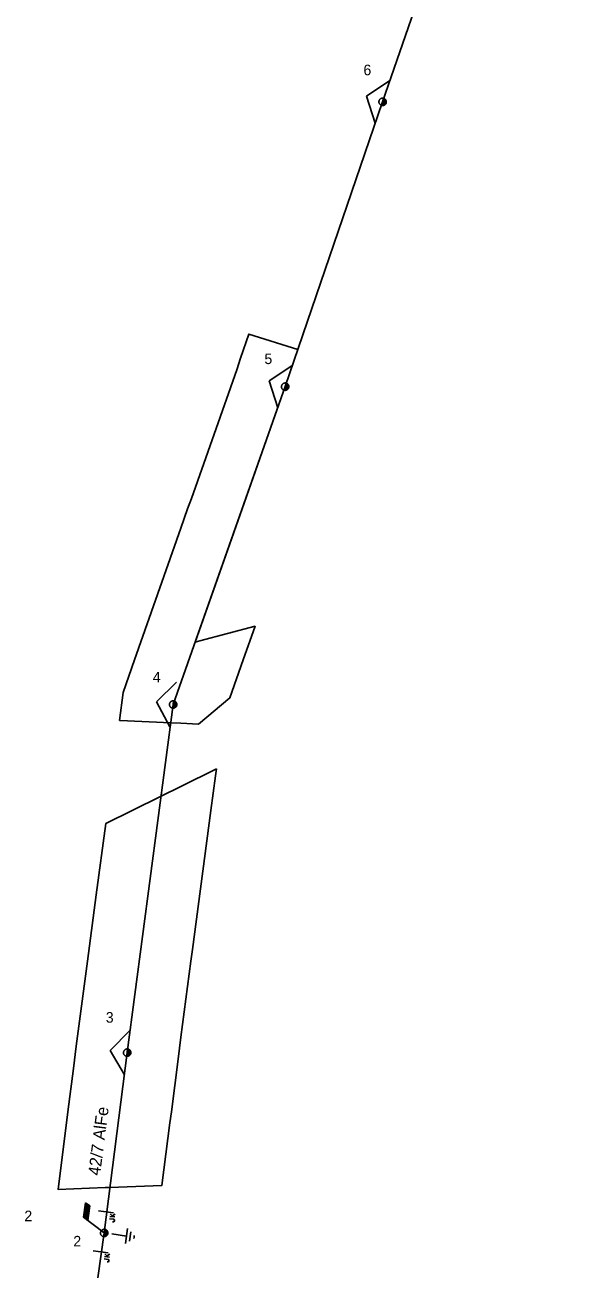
# Model space of a CAD drawing. Extents: x -536397 to -535454, y -1201642 to -1200953.
# Drawn here: x -535913.3 to -535821.2, y -1201640.1 to -1201432.2 of the extents above; entities that cross this region are included whole.
import ezdxf

# ---------------------------------------------------------------- set-up
doc = ezdxf.new("R2010")
doc.units = 0
for name, color, linetype in [('Default', 7, 'Continuous'), ('Vrstva 11', 7, 'Continuous'), ('Vrstva 12', 7, 'Continuous'), ('Vrstva 13', 7, 'Continuous'), ('Vrstva 14', 7, 'Continuous'), ('Vrstva 15', 7, 'Continuous'), ('Vrstva 18', 7, 'Continuous'), ('Vrstva 2', 7, 'Continuous'), ('Vrstva 35', 7, 'Continuous'), ('Vrstva 52', 7, 'Continuous'), ('Vrstva 53', 7, 'Continuous')]:
    doc.layers.add(name, color=color, linetype=linetype)

# ---------------------------------------------------------------- blocks, each defined once
blk = doc.blocks.new('VN840')
at = {"layer": 'Vrstva 15'}
for points in [[(-0.01, 1.41), (-0.01, -1.09)], [(-1.51, -1.24), (-1.51, -1.15)], [(-1.48, -1.35), (-1.51, -1.24)], [(-1.33, -1.42), (-1.48, -1.35)], [(-1.27, -1.42), (-1.33, -1.42)], [(-1.13, -1.35), (-1.27, -1.42)], [(-1.09, -1.24), (-1.13, -1.35)], [(-1.09, -0.59), (-1.09, -1.24)], [(-0.68, -0.59), (-0.68, -1.42)], [(-0.68, -1.11), (-0.27, -0.59)], [(-0.54, -0.94), (-0.2, -1.42)]]:
    blk.add_lwpolyline(points, dxfattribs=at)
blk = doc.blocks.new('VN860')
at = {"layer": 'Vrstva 15'}
for points in [[(-3.74, 0), (0.01, 2.82)], [(0.01, 2.82), (3.76, 0)]]:
    blk.add_lwpolyline(points, dxfattribs=at)
blk = doc.blocks.new('VN440')
at = {"layer": 'Vrstva 2'}
for points in [[(1.22, 0), (1.21, 0.13), (1.19, 0.25), (1.16, 0.38), (1.11, 0.5), (1.05, 0.61), (0.98, 0.72), (0.9, 0.82), (0.81, 0.91), (0.71, 0.99), (0.6, 1.06), (0.49, 1.12), (0.37, 1.16), (0.25, 1.2), (0.12, 1.22), (-0.01, 1.22), (-0.14, 1.22), (-0.26, 1.2), (-0.39, 1.16), (-0.51, 1.12), (-0.62, 1.06), (-0.73, 0.99), (-0.83, 0.91), (-0.92, 0.82), (-1, 0.72), (-1.07, 0.61), (-1.13, 0.5), (-1.18, 0.38), (-1.21, 0.25), (-1.23, 0.13), (-1.24, 0), (-1.23, -0.13), (-1.21, -0.26), (-1.18, -0.38), (-1.13, -0.5), (-1.07, -0.62), (-1, -0.73), (-0.92, -0.83), (-0.83, -0.92), (-0.73, -1), (-0.62, -1.07), (-0.51, -1.13), (-0.39, -1.17), (-0.26, -1.2), (-0.14, -1.23), (-0.01, -1.23), (0.12, -1.23), (0.25, -1.2), (0.37, -1.17), (0.49, -1.13), (0.6, -1.07), (0.71, -1), (0.81, -0.92), (0.9, -0.83), (0.98, -0.73), (1.05, -0.62), (1.11, -0.5), (1.16, -0.38), (1.19, -0.26), (1.21, -0.13), (1.22, 0)], [(-1.24, 0), (1.22, 0)], [(-1.18, -0.34), (1.1, -0.34)], [(-1.01, -0.63), (0.97, -0.63)], [(-0.74, -0.92), (0.68, -0.92)]]:
    blk.add_lwpolyline(points, dxfattribs=at)
blk = doc.blocks.new('VN810')
at = {"layer": 'Vrstva 14'}
for points in [[(0, -1.25), (0, -3.75)], [(1.25, -3.75), (-1.25, -3.75)], [(0.77, -4.37), (-0.8, -4.37)], [(0, -5), (-0.25, -5)], [(0.27, -5), (0, -5)]]:
    blk.add_lwpolyline(points, dxfattribs=at)
blk = doc.blocks.new('VN001')
at = {"layer": 'Default'}
for p, q in [((1.73, 3.03), (4.14, 3.03)), ((1.76, 3.08), (4.17, 3.08)), ((1.79, 3.13), (4.2, 3.13)), ((1.82, 3.18), (4.23, 3.18)), ((1.85, 3.23), (4.26, 3.23)), ((1.87, 3.28), (4.29, 3.28)), ((1.9, 3.33), (4.32, 3.33)), ((1.93, 3.38), (4.35, 3.38)), ((1.96, 3.43), (4.37, 3.43)), ((1.99, 3.48), (4.4, 3.48)), ((2.02, 3.53), (4.43, 3.53)), ((2.05, 3.58), (4.46, 3.58)), ((2.07, 3.63), (4.49, 3.63)), ((2.1, 3.68), (4.52, 3.68)), ((2.13, 3.73), (2.54, 3.73))]:
    blk.add_line(p, q, dxfattribs=at)
blk.add_lwpolyline([(2.13, 3.73), (0, 0)], dxfattribs=at)
blk.add_lwpolyline([(4.55, 3.73), (2.13, 3.73), (1.7, 2.98), (4.12, 2.99)], close=True, dxfattribs=at)

msp = doc.modelspace()

# ---------------------------------------------------------------- linework, layer by layer
at = {"layer": 'Vrstva 35'}
for points in [[(-535897.71, -1201547.56), (-535897.1, -1201542.93), (-535895.19, -1201537.5), (-535887.5, -1201515.66), (-535886.39, -1201512.5), (-535885.78, -1201510.78), (-535878.26, -1201489.41), (-535877.61, -1201487.5), (-535876.23, -1201483.48), (-535868.13, -1201486.05), (-535868.63, -1201487.5), (-535870.23, -1201492.2), (-535871.88, -1201496.88), (-535877.38, -1201512.5), (-535885.15, -1201534.57), (-535884.36, -1201534.36), (-535875.21, -1201531.94), (-535877.17, -1201537.5), (-535879.4, -1201543.84), (-535884.62, -1201548.17), (-535887.5, -1201548.04), (-535889.19, -1201547.96), (-535897.57, -1201547.57)], [(-535881.63, -1201555.62), (-535881.78, -1201556.78), (-535882.54, -1201562.5), (-535885.58, -1201585.58), (-535885.84, -1201587.5), (-535887.5, -1201600.12), (-535887.98, -1201603.76), (-535889.09, -1201612.5), (-535889.33, -1201614.33), (-535890.65, -1201624.7), (-535899.26, -1201625.04), (-535900.07, -1201625.07), (-535907.87, -1201625.37), (-535906.23, -1201612.5), (-535905.32, -1201605.32), (-535904.84, -1201601.58), (-535902.98, -1201587.5), (-535901.53, -1201576.53), (-535899.97, -1201564.68), (-535895.56, -1201562.5), (-535890.8, -1201560.15), (-535887.5, -1201558.52)]]:
    msp.add_lwpolyline(points, close=True, dxfattribs=at)
at = {"layer": 'Vrstva 52'}
for points in [[(-535900.22, -1201632.59), (-535896.41, -1201602.67), (-535888.79, -1201544.92), (-535870.23, -1201492.2), (-535854.08, -1201444.95), (-535839.27, -1201402.16), (-535821.22, -1201351.74)], [(-535901.25, -1201640.05), (-535900.22, -1201632.59)]]:
    msp.add_lwpolyline(points, dxfattribs=at)

# ---------------------------------------------------------------- block references
at = {"layer": 'Vrstva 11', "rotation": 82.16037223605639}
msp.add_blockref('VN001', (-535900.22, -1201632.59), dxfattribs=at)
at = {"layer": 'Vrstva 13', "xscale": 0.5}
for p, yscale, rotation in [((-535854.08, -1201444.95), 0.5, 71.12953331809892), ((-535870.23, -1201492.2), 0.5, 70.60537496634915), ((-535888.79, -1201544.92), 0.5000000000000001, 82.48322216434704), ((-535896.41, -1201602.67), 0.5, 82.74278051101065), ((-535900.22, -1201632.59), 0.49999999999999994, 82.16094441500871)]:
    msp.add_blockref('VN440', p, dxfattribs=dict(at, yscale=yscale, rotation=rotation))
at = {"layer": 'Vrstva 15', "rotation": 82.16137222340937}
msp.add_blockref('VN810', (-535900.22, -1201632.59), dxfattribs=at)
at = {"layer": 'Vrstva 18'}
for name, p, rotation in [('VN860', (-535854.08, -1201444.95), 71.12941941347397), ('VN860', (-535870.23, -1201492.2), 70.605499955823), ('VN860', (-535888.79, -1201544.92), 81.3135889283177), ('VN860', (-535896.41, -1201602.67), 82.7432222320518), ('VN840', (-535899.77, -1201629.09), 82.7430361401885), ('VN840', (-535900.65, -1201635.72), 82.16127775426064)]:
    msp.add_blockref(name, p, dxfattribs=dict(at, rotation=rotation))

# ---------------------------------------------------------------- texts
at = {"layer": 'Vrstva 12'}
msp.add_text('2', height=1.75, dxfattribs=at).set_placement((-535913.45, -1201630.64))
at = {"layer": 'Vrstva 14'}
for s, p in [('6', (-535857.26, -1201440.54)), ('5', (-535873.67, -1201488.46)), ('4', (-535892.17, -1201541.27)), ('3', (-535899.96, -1201597.71)), ('2', (-535905.34, -1201634.83))]:
    msp.add_text(s, height=1.75, dxfattribs=at).set_placement(p)
at = {"layer": 'Vrstva 53'}
msp.add_text('42/7 AlFe', height=2, rotation=82.743, dxfattribs=at).set_placement((-535900.91, -1201623.15))

doc.saveas('drawing.dxf')
